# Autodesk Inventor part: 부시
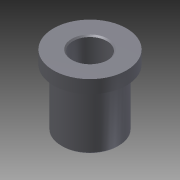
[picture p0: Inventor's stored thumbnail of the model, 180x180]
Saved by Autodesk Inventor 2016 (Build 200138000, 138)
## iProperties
Company: 한국ATC센터
Created: 2015-11
Part Number: 부시
Document SubType Name: Modeling
Designer: mdu
Density: 7.86 g/cm^3
Material: 강철, 연강
Mass: 65.5031 g
Surface Area: 42.0516 cm^2
Volume: 8.33373 cm^3
Appearance: 강철
Author: mdu
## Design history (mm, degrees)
sketch "스케치1"
  geometry: C1 r 11 at (0, 0) reference; C2 r 14 at (0, 0) reference; C3 r 11 at (0, 0) reference; 1 further point
  node "참조1"
  node "참조2"
extrude "돌출1" new body sketch "스케치1" distance "d0" = 5; taper "d1" = 0 deg
extrude "돌출2" join sketch "스케치1" distance "d2" = 24; taper "d3" = 0 deg
hole "구멍1" diameter "d6" = 13; stored, may be unused: countersink angle "d10" = 90 deg, drill point angle "d12" = 118 deg; dims "d4" = 10, "d5" = 10, "d7" = 6, "d8" = 4, "d9" = 2, "d11" = 8
chamfer "모따기1" distance "d13" = 0.5; stored, may be unused: second distance "d14" = 2, angle "d15" = 45 deg
chamfer "모따기2" distance "d16" = 0.5; stored, may be unused: second distance "d17" = 2, angle "d18" = 45 deg
node "솔리드1"
